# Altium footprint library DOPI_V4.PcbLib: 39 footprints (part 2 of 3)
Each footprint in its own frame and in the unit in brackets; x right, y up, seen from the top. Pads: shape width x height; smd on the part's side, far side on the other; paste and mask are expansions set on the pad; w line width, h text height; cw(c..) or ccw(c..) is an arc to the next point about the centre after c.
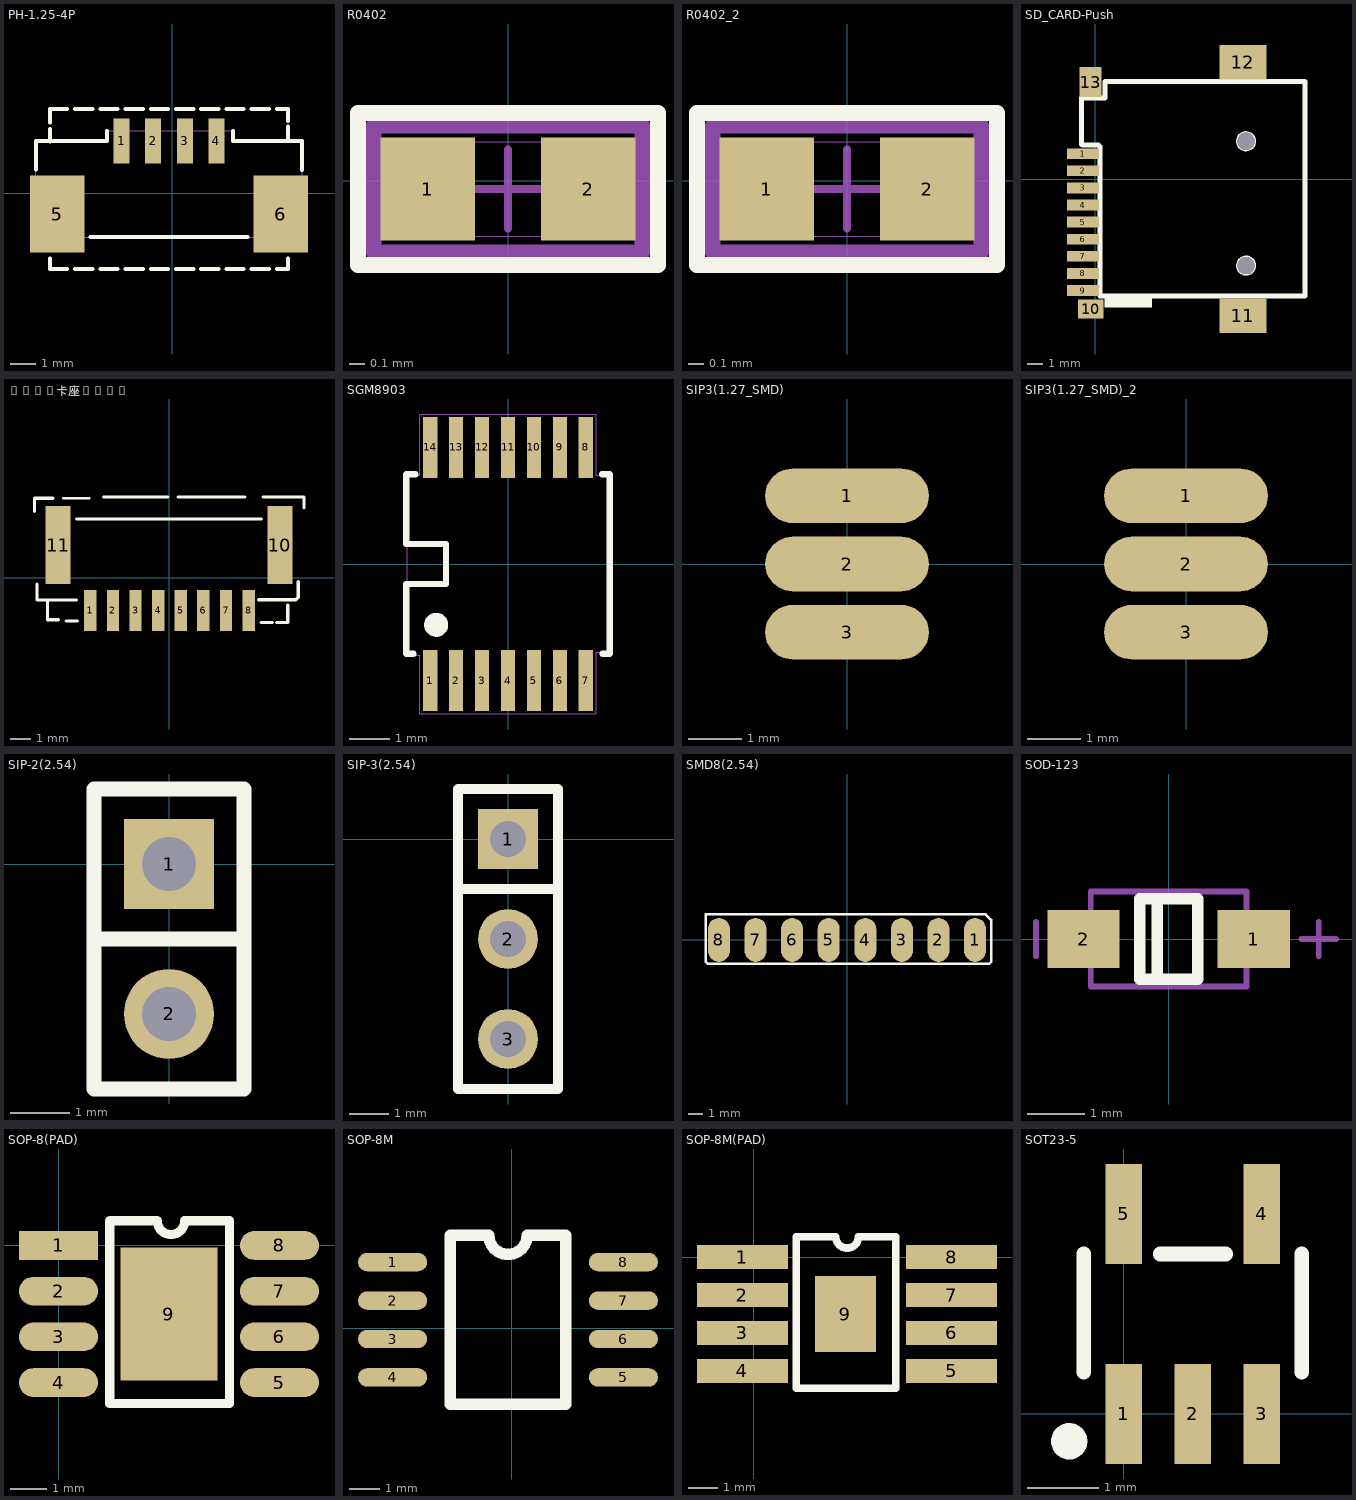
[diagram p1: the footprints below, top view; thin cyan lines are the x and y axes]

## PH-1.25-4P [mil]
pads (6):
  rect 25x70 smd mask+3: 1(-78.82,82) 2(-29.61,82) 3(19.61,82) 4(68.82,82)
  rect 85x120 smd mask+3: 5(-179.21,-32.17) 6(169.21,-32.17)
Top Overlay:
  lines w6: -212.67,37 -212.67,82 -101.57,82 -101.57,98 ; -191.02,-101.17 -191.02,-118 -163.77,-118 ; -191.02,80.97 -191.02,100.89 ; -191.02,110.58 -191.02,132 -163.77,132 ; -151.65,-118 -124.4,-118 ; -151.65,132 -124.4,132 ; -127.71,-68 117.71,-68 ; -112.28,-118 -85.03,-118 ; -112.28,132 -85.03,132 ; -72.91,-118 -45.66,-118 ; -72.91,132 -45.66,132 ; -33.54,-118 -6.29,-118 ; -33.54,132 -6.29,132 ; 5.83,-118 33.08,-118 ; 5.83,132 33.08,132 ; 45.2,-118 72.45,-118 ; 45.2,132 72.45,132 ; 84.57,-118 111.82,-118 ; 84.57,132 111.82,132 ; 95,98 95,82 202.67,82 202.67,36.83 ; 123.94,-118 151.19,-118 ; 123.94,132 151.19,132 ; 163.31,-118 180.38,-118 ; 163.31,132 180.38,132 ; 181.02,-118 181.02,-101.17 ; 181.02,82 181.02,104.43 ; 181.02,113.2 181.02,132
Mechanical 16:
  lines w1: -212.67,-68 202.67,-68 202.67,82 95,82 95,98 -101.57,98 -101.57,82 -212.67,82 -212.67,-68

## R0402 [mm]
pads (2):
  rect 0.6x0.65 smd: 1(-0.508,-0.051) 2(0.508,-0.051)
Top Overlay:
  lines w0.102: -0.95,-0.533 -0.95,0.432 0.95,0.432 0.95,-0.533 -0.95,-0.533
Mechanical 15:
  lines w0.1: -0.85,-0.451 0.85,-0.451 0.85,0.349 -0.85,0.349 -0.85,-0.451
  text "1" at -0.082,-0.276 h0.38
Mechanical 16:
  lines w0.001: -0.55,-0.351 0.55,-0.351 0.55,0.249 -0.55,0.249 -0.55,-0.351
  lines w0.05: -0.25,-0.051 0.25,-0.051 ; 0,-0.301 0,0.199 ; -0.95,-0.551 0.95,-0.551 0.95,0.449 -0.95,0.449 -0.95,-0.551
3D body: height 0.35, standoff 0, extent -0.475,-0.305 0.525,0.195

## R0402_2 [mm]
pads (2):
  rect 0.6x0.65 smd: 1(-0.508,-0.051) 2(0.508,-0.051)
Top Overlay:
  lines w0.102: -0.95,-0.533 -0.95,0.432 0.95,0.432 0.95,-0.533 -0.95,-0.533
Mechanical 15:
  lines w0.1: -0.85,-0.451 0.85,-0.451 0.85,0.349 -0.85,0.349 -0.85,-0.451
  text "1" at -0.082,-0.276 h0.38
Mechanical 16:
  lines w0.001: -0.55,-0.351 0.55,-0.351 0.55,0.249 -0.55,0.249 -0.55,-0.351
  lines w0.05: -0.25,-0.051 0.25,-0.051 ; 0,-0.301 0,0.199 ; -0.95,-0.551 0.95,-0.551 0.95,0.449 -0.95,0.449 -0.95,-0.551
3D body: height 0.35, standoff 0, extent -0.475,-0.305 0.525,0.195

## SD_CARD-Push [mm] "弹出式TF卡座子"
pads (15):
  rect 2.057x0.7 smd: 1(-0.801,1.642) 2(-0.801,0.542) 3(-0.801,-0.558) 4(-0.801,-1.658) 5(-0.801,-2.758) 6(-0.801,-3.858) 7(-0.801,-4.958) 8(-0.801,-6.058) 9(-0.801,-7.158)
  rect 1.629x1.225 smd: 10(-0.301,-8.358)
  rect 3x2.2 smd: 11(9.5,-8.778) 12(9.5,7.52)
  rect 1.4x1.93 smd: 13(-0.301,6.242)
  round 1.1 hole 1.1: ""(9.699,-5.558) ""(9.699,2.442)
Top Overlay:
  circle w0.1: c9.699,-5.558 r0.6
  circle w0.1: c9.699,2.442 r0.6
  region: 3.648,-8.258 3.648,-7.558 0.598,-7.558 0.598,-8.258
  lines w0.33: 0.624,6.217 0.624,5.217 -0.876,5.217 -0.876,2.242 -0.826,2.192 0.199,2.192 0.299,2.092 0.299,-7.508 13.499,-7.508 13.499,6.292 0.624,6.292

## SDIO卡座(8P) [mm]
pads (10):
  rect 0.6x2 smd mask+0.076: 1(-3.826,-1.587) 2(-2.726,-1.587) 3(-1.626,-1.587) 4(-0.526,-1.587) 5(0.573,-1.587) 6(1.673,-1.587) 7(2.773,-1.587) 8(3.873,-1.587)
  rect 1.2x3.8 smd mask+0.076: 10(5.397,1.587) 11(-5.397,1.587)
Top Overlay:
  lines w0.127: -5.143,3.873 -3.873,3.873
  lines w0.152: -6.54,3.238 -6.54,3.873 -5.651,3.873 ; -6.413,-0.296 -6.413,-1.079 -4.508,-1.079 ; -5.905,-1.182 -5.905,-2.042 -5.375,-2.042 ; -5.016,-2.095 -4.456,-2.095 ; -4.508,2.857 4.508,2.857 ; -3.192,3.931 -0.053,3.931 ; 0.447,3.931 3.685,3.931 ; 4.356,-1.069 6.17,-1.069 6.286,-0.953 6.286,-0.191 ; 4.479,-2.169 5.039,-2.169 ; 4.584,3.931 6.574,3.931 6.574,3.403 ; 5.241,-2.169 5.779,-2.169 5.779,-1.337

## SGM8903 [mil]
pads (14):
  rect 14x60 smd mask+3: 1(-76.77,-115) 2(-51.18,-115) 3(-25.59,-115) 4(0,-115) 5(25.59,-115) 6(51.18,-115) 7(76.77,-115) 8(76.77,115) 9(51.18,115) 10(25.59,115) 11(0,115) 12(-25.59,115) 13(-51.18,115) 14(-76.77,115)
Top Overlay:
  circle w11.81: c-70.9,-60 r5.9
  lines w6: -93.27,-88.58 -100.39,-88.58 -100.39,-19.69 -61.02,-19.69 -61.02,19.69 -100.39,19.69 -100.39,88.58 -91.41,88.58 ; 92.87,88.58 100.39,88.58 100.39,-88.58 93.08,-88.58
Mechanical 16:
  lines w1: 87.01,90 87.01,87.4 100.39,87.4 100.39,-87.01 87,-87.01 87,-148 -87,-148 -87,-90 -99.61,-90 -99.61,87.4 -87,87.4 -87,148 87,148 87,90 ; 87,90 87.01,90

## SIP3(1.27_SMD) [mil]
pads (3):
  oval 120x40 smd: 1(0,50) 2(0,0) 3(0,-50)

## SIP3(1.27_SMD)_2 [mil]
pads (3):
  oval 120x40 smd: 1(0,50) 2(0,0) 3(0,-50)

## SIP-2(2.54) [mil]
pads (2):
  rect 60x60 hole 36: 1(0,0)
  round 60 hole 36: 2(0,-100)
Top Overlay:
  lines w10: -50,-50 50,-50 ; -50,-150 -50,50 50,50 50,-150 -50,-150

## SIP-3(2.54) [mil]
pads (3):
  rect 60x60 hole 36: 1(0,0)
  round 60 hole 36: 2(0,-100) 3(0,-200)
Top Overlay:
  lines w10: -50,-50 50,-50 ; -50,-250 -50,50 50,50 50,-250 -50,-250

## SMD8(2.54) [mil]
pads (8):
  oval 60x120 smd: 1(350,0) 2(250,0) 3(150,0) 4(50,0) 5(-50,0) 6(-150,0) 7(-250,0) 8(-350,0)
Top Overlay:
  lines w7: -386,-60.04 -381,-65.04 389,-65.04 394,-60.04 394,54.96 379,69.96 -386,69.96 -386,-60.04

## SOD-123 [mm]
pads (2):
  rect 1.25x1 smd: 1(1.475,0) 2(-1.475,0)
Top Overlay:
  lines w0.2: -0.2,-0.7 -0.2,0.7 ; -0.5,-0.7 0.5,-0.7 0.5,0.7 -0.5,0.7 -0.5,-0.7
Mechanical 13:
  lines w0.1: -1.35,-0.825 -1.35,0.825 1.35,0.825 1.35,-0.825 -1.35,-0.825
Mechanical 15:
  lines w0.1: -2.3,-0.3 -2.3,0.3 ; 2.3,0 2.9,0 ; 2.6,-0.3 2.6,0.3
3D body: height 1.35, standoff 0, extent -1.85,-0.775 1.85,0.775

## SOP-8(PAD) [mm] "AOZ1284 4A输出电源芯片的封装"
pads (9):
  rect 2.2x0.8 smd: 1(0,0)
  oval 2.2x0.8 smd: 2(0,-1.27) 3(0,-2.54) 4(0,-3.81) 5(6.14,-3.81) 6(6.14,-2.54) 7(6.14,-1.27) 8(6.14,0)
  rect 2.71x3.7 smd: 9(3.07,-1.905)
Top Overlay:
  lines w0.254: 1.422,-4.394 4.75,-4.394 4.75,0.686 3.505,0.686 cw(c3.124,0.686) 2.743,0.686 1.422,0.686 1.422,-4.394

## SOP-8M [mil]
pads (8):
  oval 90x24 smd: 1(-155,86) 2(-155,36) 3(-155,-14) 4(-155,-64) 5(145,-64) 6(145,-14) 7(145,36) 8(145,86)
Top Overlay:
  lines w15: -80,-99 -80,121 -30,121 ccw(c-5,121) 20,121 70,121 70,-99 -80,-99
3D body "SO-8.STEP": height 57, standoff 0, extent -119.75,-84 107.75,109

## SOP-8M(PAD) [mil] "nand"
pads (9):
  rect 120x31.5 smd: 1(-15,0) 2(-15,-50) 3(-15,-100) 4(-15,-150) 5(260.73,-150) 6(260.73,-100) 7(260.73,-50) 8(260.73,0)
  rect 80x100 smd: 9(120.87,-75)
Top Overlay:
  lines w10: 56,-173 187,-173 187,27 138,27 cw(c123,27) 108,27 56,27 56,-173

## SOT23-5 [mil]
pads (5):
  rect 20x55 smd: 1(0,0) 2(38,0) 3(76,0) 4(76,110) 5(0,110)
Top Overlay:
  circle w10: c-30,-15 r5
  lines w8: -22,23 -22,88 ; 20,88 56,88 ; 98,23 98,88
